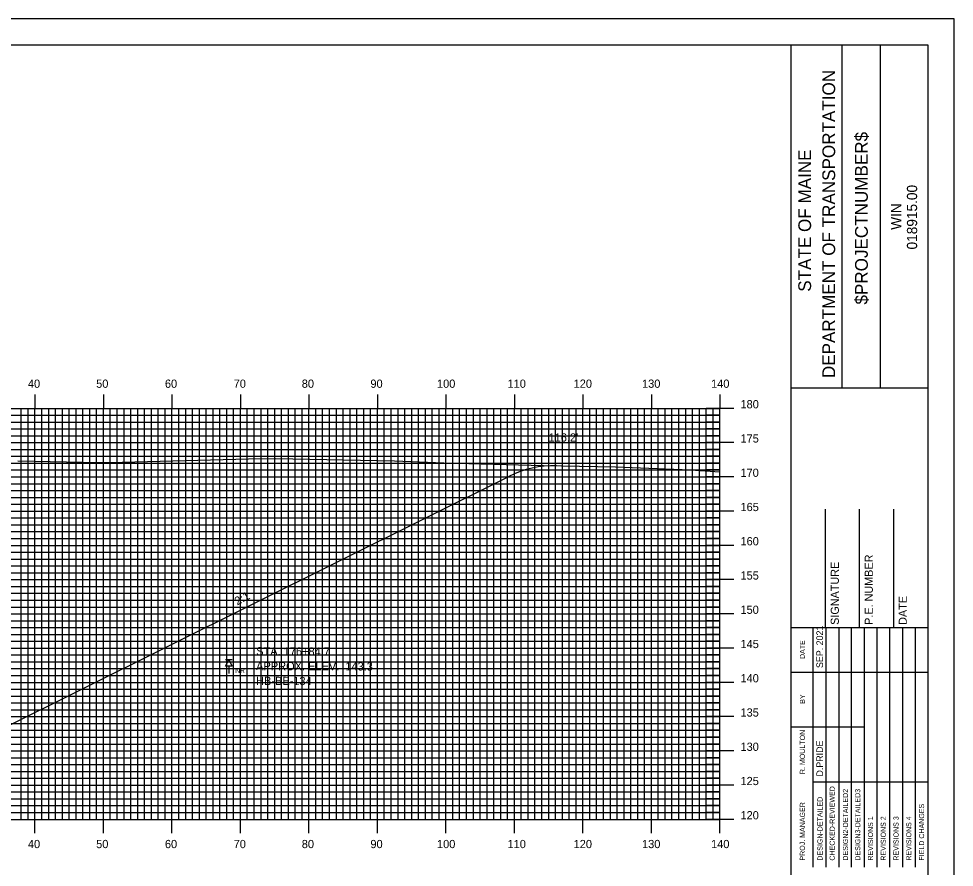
# Model space of a CAD drawing. Extents: x 1784615 to 1784958, y 442591 to 442811.
# Drawn here: x 1784818.1 to 1784954.7, y 442686.7 to 442810.5 of the extents above; entities that cross this region are included whole.
import ezdxf

# ---------------------------------------------------------------- set-up
doc = ezdxf.new("R2010")
doc.units = 0
for name, color, linetype in [('ANNOTATION', 7, 'Continuous'), ('BORDER', 7, 'Continuous'), ('BORING - NO REFUSAL', 7, 'Continuous'), ('D_Roadway_SlopeLines', 7, 'Continuous'), ('D_Text_Standard', 7, 'Continuous'), ('H_V ANNOTATION', 7, 'Continuous'), ('MAJOR', 7, 'Continuous'), ('MINOR', 7, 'Continuous'), ('PLOT BOUNDARY', 7, 'Continuous'), ('S_Roadway_Centerline', 7, 'Continuous')]:
    doc.layers.add(name, color=color, linetype=linetype)

msp = doc.modelspace()

# ---------------------------------------------------------------- linework, layer by layer
at = {"layer": 'BORDER'}
for p, q in [((1784930.91, 442596.67), (1784930.91, 442806.67)), ((1784938.37, 442756.66), (1784938.37, 442806.66)), ((1784943.96, 442756.66), (1784943.96, 442806.66)), ((1784930.91, 442756.65), (1784950.91, 442756.65)), ((1784930.91, 442756.65), (1784950.91, 442756.65)), ((1784935.91, 442721.67), (1784935.91, 442738.97)), ((1784935.91, 442721.67), (1784935.91, 442738.97)), ((1784940.91, 442721.67), (1784940.91, 442738.97)), ((1784940.91, 442721.67), (1784940.91, 442738.97)), ((1784945.91, 442721.67), (1784945.91, 442738.97)), ((1784945.91, 442721.67), (1784945.91, 442738.97)), ((1784930.91, 442721.67), (1784950.91, 442721.67)), ((1784930.91, 442721.67), (1784950.91, 442721.67))]:
    msp.add_line(p, q, dxfattribs=at)
msp.add_lwpolyline([(1784630.91, 442596.67), (1784950.91, 442596.67), (1784950.91, 442806.67), (1784630.91, 442806.67)], close=True, dxfattribs=at)
for points in [[(1784934.14, 442715.17), (1784934.14, 442721.67)], [(1784934.14, 442715.17), (1784934.14, 442721.67)], [(1784936.01, 442686.68), (1784936.01, 442721.67)], [(1784936.01, 442686.68), (1784936.01, 442721.67)], [(1784937.87, 442721.67), (1784937.87, 442686.68)], [(1784937.87, 442721.67), (1784937.87, 442686.68)], [(1784939.73, 442686.68), (1784939.73, 442721.67)], [(1784939.73, 442686.68), (1784939.73, 442721.67)], [(1784941.6, 442686.68), (1784941.6, 442721.67)], [(1784941.6, 442686.68), (1784941.6, 442721.67)], [(1784943.46, 442686.68), (1784943.46, 442721.67)], [(1784943.46, 442686.68), (1784943.46, 442721.67)], [(1784945.32, 442686.68), (1784945.32, 442721.67)], [(1784945.32, 442686.68), (1784945.32, 442721.67)], [(1784947.19, 442686.68), (1784947.19, 442721.67)], [(1784947.19, 442686.68), (1784947.19, 442721.67)], [(1784949.05, 442686.68), (1784949.05, 442721.67)], [(1784949.05, 442686.68), (1784949.05, 442721.67)], [(1784934.14, 442686.68), (1784934.14, 442720.26)], [(1784934.14, 442686.68), (1784934.14, 442720.26)], [(1784930.91, 442715.17), (1784950.91, 442715.17)], [(1784930.91, 442715.17), (1784950.91, 442715.17)], [(1784930.91, 442707.17), (1784934.14, 442707.17)], [(1784930.91, 442707.17), (1784934.14, 442707.17)], [(1784934.14, 442707.17), (1784941.6, 442707.17)], [(1784934.14, 442707.17), (1784941.6, 442707.17)], [(1784934.14, 442699.17), (1784950.91, 442699.17)], [(1784934.14, 442699.17), (1784950.91, 442699.17)]]:
    msp.add_lwpolyline(points, dxfattribs=at)
at = {"layer": 'BORING - NO REFUSAL'}
for p, q in [((1784849.29, 442716.97), (1784848.33, 442716.97)), ((1784848.81, 442716.01), (1784848.81, 442714.95))]:
    msp.add_line(p, q, dxfattribs=at)
msp.add_lwpolyline([(1784848.81, 442716.97), (1784849.29, 442716.01), (1784848.33, 442716.01)], close=True, dxfattribs=at)
at = {"layer": 'D_Roadway_SlopeLines'}
msp.add_line((1784810.7, 442704.42), (1784889.7, 442743.74), dxfattribs=at)
msp.add_arc((1784896.39, 442730.31), 15, 88.9414, 116.4579, dxfattribs=at)
at = {"layer": 'MAJOR'}
for p, q in [((1784820.51, 442755.67), (1784820.51, 442753.67)), ((1784830.51, 442755.67), (1784830.51, 442753.67)), ((1784840.51, 442755.67), (1784840.51, 442753.67)), ((1784850.51, 442755.67), (1784850.51, 442753.67)), ((1784860.51, 442755.67), (1784860.51, 442753.67)), ((1784870.51, 442755.67), (1784870.51, 442753.67)), ((1784880.51, 442755.67), (1784880.51, 442753.67)), ((1784890.51, 442755.67), (1784890.51, 442753.67)), ((1784900.51, 442755.67), (1784900.51, 442753.67)), ((1784910.51, 442755.67), (1784910.51, 442753.67)), ((1784920.51, 442755.67), (1784920.51, 442753.67)), ((1784640.51, 442753.67), (1784920.51, 442753.67)), ((1784640.51, 442753.67), (1784920.51, 442753.67)), ((1784820.51, 442693.67), (1784820.51, 442753.67)), ((1784830.51, 442693.67), (1784830.51, 442753.67)), ((1784840.51, 442693.67), (1784840.51, 442753.67)), ((1784850.51, 442693.67), (1784850.51, 442753.67)), ((1784860.51, 442693.67), (1784860.51, 442753.67)), ((1784870.51, 442693.67), (1784870.51, 442753.67)), ((1784880.51, 442693.67), (1784880.51, 442753.67)), ((1784890.51, 442693.67), (1784890.51, 442753.67)), ((1784900.51, 442693.67), (1784900.51, 442753.67)), ((1784910.51, 442693.67), (1784910.51, 442753.67)), ((1784922.52, 442753.67), (1784918.51, 442753.67)), ((1784920.51, 442693.67), (1784920.51, 442753.67)), ((1784920.51, 442693.67), (1784920.51, 442753.67)), ((1784640.51, 442748.67), (1784920.51, 442748.67)), ((1784922.52, 442748.67), (1784918.51, 442748.67)), ((1784640.51, 442743.67), (1784920.51, 442743.67)), ((1784922.52, 442743.67), (1784918.51, 442743.67)), ((1784640.51, 442738.67), (1784920.51, 442738.67)), ((1784922.52, 442738.67), (1784918.51, 442738.67)), ((1784640.51, 442733.67), (1784920.51, 442733.67)), ((1784922.52, 442733.67), (1784918.51, 442733.67)), ((1784640.51, 442728.67), (1784920.51, 442728.67)), ((1784922.52, 442728.67), (1784918.51, 442728.67)), ((1784640.51, 442723.67), (1784920.51, 442723.67)), ((1784922.52, 442723.67), (1784918.51, 442723.67)), ((1784640.51, 442718.67), (1784920.51, 442718.67)), ((1784922.52, 442718.67), (1784918.51, 442718.67)), ((1784640.51, 442713.67), (1784920.51, 442713.67)), ((1784922.52, 442713.67), (1784918.51, 442713.67)), ((1784640.51, 442708.67), (1784920.51, 442708.67)), ((1784922.52, 442708.67), (1784918.51, 442708.67)), ((1784640.51, 442703.67), (1784920.51, 442703.67)), ((1784922.52, 442703.67), (1784918.51, 442703.67)), ((1784640.51, 442698.67), (1784920.51, 442698.67)), ((1784922.52, 442698.67), (1784918.51, 442698.67)), ((1784640.51, 442693.67), (1784920.51, 442693.67)), ((1784640.51, 442693.67), (1784920.51, 442693.67)), ((1784820.51, 442691.66), (1784820.51, 442693.67)), ((1784830.51, 442691.66), (1784830.51, 442693.67)), ((1784840.51, 442691.66), (1784840.51, 442693.67)), ((1784850.51, 442691.66), (1784850.51, 442693.67)), ((1784860.51, 442691.66), (1784860.51, 442693.67)), ((1784870.51, 442691.66), (1784870.51, 442693.67)), ((1784880.51, 442691.66), (1784880.51, 442693.67)), ((1784890.51, 442691.66), (1784890.51, 442693.67)), ((1784900.51, 442691.66), (1784900.51, 442693.67)), ((1784910.51, 442691.66), (1784910.51, 442693.67)), ((1784922.52, 442693.67), (1784918.51, 442693.67)), ((1784920.51, 442691.66), (1784920.51, 442693.67))]:
    msp.add_line(p, q, dxfattribs=at)
at = {"layer": 'MINOR'}
for p, q in [((1784818.51, 442693.67), (1784818.51, 442753.67)), ((1784819.51, 442693.67), (1784819.51, 442753.67)), ((1784821.51, 442693.67), (1784821.51, 442753.67)), ((1784822.51, 442693.67), (1784822.51, 442753.67)), ((1784823.51, 442693.67), (1784823.51, 442753.67)), ((1784824.51, 442693.67), (1784824.51, 442753.67)), ((1784825.51, 442693.67), (1784825.51, 442753.67)), ((1784826.51, 442693.67), (1784826.51, 442753.67)), ((1784827.51, 442693.67), (1784827.51, 442753.67)), ((1784828.51, 442693.67), (1784828.51, 442753.67)), ((1784829.51, 442693.67), (1784829.51, 442753.67)), ((1784831.51, 442693.67), (1784831.51, 442753.67)), ((1784832.51, 442693.67), (1784832.51, 442753.67)), ((1784833.51, 442693.67), (1784833.51, 442753.67)), ((1784834.51, 442693.67), (1784834.51, 442753.67)), ((1784835.51, 442693.67), (1784835.51, 442753.67)), ((1784836.51, 442693.67), (1784836.51, 442753.67)), ((1784837.51, 442693.67), (1784837.51, 442753.67)), ((1784838.51, 442693.67), (1784838.51, 442753.67)), ((1784839.51, 442693.67), (1784839.51, 442753.67)), ((1784841.51, 442693.67), (1784841.51, 442753.67)), ((1784842.51, 442693.67), (1784842.51, 442753.67)), ((1784843.51, 442693.67), (1784843.51, 442753.67)), ((1784844.51, 442693.67), (1784844.51, 442753.67)), ((1784845.51, 442693.67), (1784845.51, 442753.67)), ((1784846.51, 442693.67), (1784846.51, 442753.67)), ((1784847.51, 442693.67), (1784847.51, 442753.67)), ((1784848.51, 442693.67), (1784848.51, 442753.67)), ((1784849.51, 442693.67), (1784849.51, 442753.67)), ((1784851.51, 442693.67), (1784851.51, 442753.67)), ((1784852.51, 442693.67), (1784852.51, 442753.67)), ((1784853.51, 442693.67), (1784853.51, 442753.67)), ((1784854.51, 442693.67), (1784854.51, 442753.67)), ((1784855.51, 442693.67), (1784855.51, 442753.67)), ((1784856.51, 442693.67), (1784856.51, 442753.67)), ((1784857.51, 442693.67), (1784857.51, 442753.67)), ((1784858.51, 442693.67), (1784858.51, 442753.67)), ((1784859.51, 442693.67), (1784859.51, 442753.67)), ((1784861.51, 442693.67), (1784861.51, 442753.67)), ((1784862.51, 442693.67), (1784862.51, 442753.67)), ((1784863.51, 442693.67), (1784863.51, 442753.67)), ((1784864.51, 442693.67), (1784864.51, 442753.67)), ((1784865.51, 442693.67), (1784865.51, 442753.67)), ((1784866.51, 442693.67), (1784866.51, 442753.67)), ((1784867.51, 442693.67), (1784867.51, 442753.67)), ((1784868.51, 442693.67), (1784868.51, 442753.67)), ((1784869.51, 442693.67), (1784869.51, 442753.67)), ((1784871.51, 442693.67), (1784871.51, 442753.67)), ((1784872.51, 442693.67), (1784872.51, 442753.67)), ((1784873.51, 442693.67), (1784873.51, 442753.67)), ((1784874.51, 442693.67), (1784874.51, 442753.67)), ((1784875.51, 442693.67), (1784875.51, 442753.67)), ((1784876.51, 442693.67), (1784876.51, 442753.67)), ((1784877.51, 442693.67), (1784877.51, 442753.67)), ((1784878.51, 442693.67), (1784878.51, 442753.67)), ((1784879.51, 442693.67), (1784879.51, 442753.67)), ((1784881.51, 442693.67), (1784881.51, 442753.67)), ((1784882.51, 442693.67), (1784882.51, 442753.67)), ((1784883.51, 442693.67), (1784883.51, 442753.67)), ((1784884.51, 442693.67), (1784884.51, 442753.67)), ((1784885.51, 442693.67), (1784885.51, 442753.67)), ((1784886.51, 442693.67), (1784886.51, 442753.67)), ((1784887.51, 442693.67), (1784887.51, 442753.67)), ((1784888.51, 442693.67), (1784888.51, 442753.67)), ((1784889.51, 442693.67), (1784889.51, 442753.67)), ((1784891.51, 442693.67), (1784891.51, 442753.67)), ((1784892.51, 442693.67), (1784892.51, 442753.67)), ((1784893.51, 442693.67), (1784893.51, 442753.67)), ((1784894.51, 442693.67), (1784894.51, 442753.67)), ((1784895.51, 442693.67), (1784895.51, 442753.67)), ((1784896.51, 442693.67), (1784896.51, 442753.67)), ((1784897.51, 442693.67), (1784897.51, 442753.67)), ((1784898.51, 442693.67), (1784898.51, 442753.67)), ((1784899.51, 442693.67), (1784899.51, 442753.67)), ((1784901.51, 442693.67), (1784901.51, 442753.67)), ((1784902.51, 442693.67), (1784902.51, 442753.67)), ((1784903.51, 442693.67), (1784903.51, 442753.67)), ((1784904.51, 442693.67), (1784904.51, 442753.67)), ((1784905.51, 442693.67), (1784905.51, 442753.67)), ((1784906.51, 442693.67), (1784906.51, 442753.67)), ((1784907.51, 442693.67), (1784907.51, 442753.67)), ((1784908.51, 442693.67), (1784908.51, 442753.67)), ((1784909.51, 442693.67), (1784909.51, 442753.67)), ((1784911.51, 442693.67), (1784911.51, 442753.67)), ((1784912.51, 442693.67), (1784912.51, 442753.67)), ((1784913.51, 442693.67), (1784913.51, 442753.67)), ((1784914.51, 442693.67), (1784914.51, 442753.67)), ((1784915.51, 442693.67), (1784915.51, 442753.67)), ((1784916.51, 442693.67), (1784916.51, 442753.67)), ((1784917.51, 442693.67), (1784917.51, 442753.67)), ((1784918.51, 442693.67), (1784918.51, 442753.67)), ((1784919.51, 442693.67), (1784919.51, 442753.67)), ((1784640.51, 442752.67), (1784920.51, 442752.67)), ((1784920.51, 442752.67), (1784918.51, 442752.67)), ((1784640.51, 442751.67), (1784920.51, 442751.67)), ((1784920.51, 442751.67), (1784918.51, 442751.67)), ((1784640.51, 442750.67), (1784920.51, 442750.67)), ((1784640.51, 442749.67), (1784920.51, 442749.67)), ((1784920.51, 442750.67), (1784918.51, 442750.67)), ((1784920.51, 442749.67), (1784918.51, 442749.67)), ((1784640.51, 442747.67), (1784920.51, 442747.67)), ((1784640.51, 442746.67), (1784920.51, 442746.67)), ((1784920.51, 442747.67), (1784918.51, 442747.67)), ((1784920.51, 442746.67), (1784918.51, 442746.67)), ((1784640.51, 442745.67), (1784920.51, 442745.67)), ((1784920.51, 442745.67), (1784918.51, 442745.67)), ((1784640.51, 442744.67), (1784920.51, 442744.67)), ((1784920.51, 442744.67), (1784918.51, 442744.67)), ((1784640.51, 442742.67), (1784920.51, 442742.67)), ((1784920.51, 442742.67), (1784918.51, 442742.67)), ((1784640.51, 442741.67), (1784920.51, 442741.67)), ((1784920.51, 442741.67), (1784918.51, 442741.67)), ((1784640.51, 442740.67), (1784920.51, 442740.67)), ((1784920.51, 442740.67), (1784918.51, 442740.67)), ((1784640.51, 442739.67), (1784920.51, 442739.67)), ((1784920.51, 442739.67), (1784918.51, 442739.67)), ((1784640.51, 442737.67), (1784920.51, 442737.67)), ((1784920.51, 442737.67), (1784918.51, 442737.67)), ((1784640.51, 442736.67), (1784920.51, 442736.67)), ((1784920.51, 442736.67), (1784918.51, 442736.67)), ((1784640.51, 442735.67), (1784920.51, 442735.67)), ((1784640.51, 442734.67), (1784920.51, 442734.67)), ((1784920.51, 442735.67), (1784918.51, 442735.67)), ((1784920.51, 442734.67), (1784918.51, 442734.67)), ((1784640.51, 442732.67), (1784920.51, 442732.67)), ((1784640.51, 442731.67), (1784920.51, 442731.67)), ((1784920.51, 442732.67), (1784918.51, 442732.67)), ((1784920.51, 442731.67), (1784918.51, 442731.67)), ((1784640.51, 442730.67), (1784920.51, 442730.67)), ((1784920.51, 442730.67), (1784918.51, 442730.67)), ((1784640.51, 442729.67), (1784920.51, 442729.67)), ((1784920.51, 442729.67), (1784918.51, 442729.67)), ((1784640.51, 442727.67), (1784920.51, 442727.67)), ((1784920.51, 442727.67), (1784918.51, 442727.67)), ((1784640.51, 442726.67), (1784920.51, 442726.67)), ((1784920.51, 442726.67), (1784918.51, 442726.67)), ((1784640.51, 442725.67), (1784920.51, 442725.67)), ((1784920.51, 442725.67), (1784918.51, 442725.67)), ((1784640.51, 442724.67), (1784920.51, 442724.67)), ((1784920.51, 442724.67), (1784918.51, 442724.67)), ((1784640.51, 442722.67), (1784920.51, 442722.67)), ((1784920.51, 442722.67), (1784918.51, 442722.67)), ((1784640.51, 442721.67), (1784920.51, 442721.67)), ((1784920.51, 442721.67), (1784918.51, 442721.67)), ((1784640.51, 442720.67), (1784920.51, 442720.67)), ((1784640.51, 442719.67), (1784920.51, 442719.67)), ((1784920.51, 442720.67), (1784918.51, 442720.67)), ((1784920.51, 442719.67), (1784918.51, 442719.67)), ((1784640.51, 442717.67), (1784920.51, 442717.67)), ((1784640.51, 442716.67), (1784920.51, 442716.67)), ((1784920.51, 442717.67), (1784918.51, 442717.67)), ((1784920.51, 442716.67), (1784918.51, 442716.67)), ((1784640.51, 442715.67), (1784920.51, 442715.67)), ((1784920.51, 442715.67), (1784918.51, 442715.67)), ((1784640.51, 442714.67), (1784920.51, 442714.67)), ((1784920.51, 442714.67), (1784918.51, 442714.67)), ((1784640.51, 442712.67), (1784920.51, 442712.67)), ((1784920.51, 442712.67), (1784918.51, 442712.67)), ((1784640.51, 442711.67), (1784920.51, 442711.67)), ((1784920.51, 442711.67), (1784918.51, 442711.67)), ((1784640.51, 442710.67), (1784920.51, 442710.67)), ((1784920.51, 442710.67), (1784918.51, 442710.67)), ((1784640.51, 442709.67), (1784920.51, 442709.67)), ((1784920.51, 442709.67), (1784918.51, 442709.67)), ((1784640.51, 442707.67), (1784920.51, 442707.67)), ((1784920.51, 442707.67), (1784918.51, 442707.67)), ((1784640.51, 442706.67), (1784920.51, 442706.67)), ((1784920.51, 442706.67), (1784918.51, 442706.67)), ((1784640.51, 442705.67), (1784920.51, 442705.67)), ((1784640.51, 442704.67), (1784920.51, 442704.67)), ((1784920.51, 442705.67), (1784918.51, 442705.67)), ((1784920.51, 442704.67), (1784918.51, 442704.67)), ((1784640.51, 442702.67), (1784920.51, 442702.67)), ((1784640.51, 442701.67), (1784920.51, 442701.67)), ((1784920.51, 442702.67), (1784918.51, 442702.67)), ((1784920.51, 442701.67), (1784918.51, 442701.67)), ((1784640.51, 442700.67), (1784920.51, 442700.67)), ((1784920.51, 442700.67), (1784918.51, 442700.67)), ((1784640.51, 442699.67), (1784920.51, 442699.67)), ((1784920.51, 442699.67), (1784918.51, 442699.67)), ((1784640.51, 442697.67), (1784920.51, 442697.67)), ((1784920.51, 442697.67), (1784918.51, 442697.67)), ((1784640.51, 442696.67), (1784920.51, 442696.67)), ((1784920.51, 442696.67), (1784918.51, 442696.67)), ((1784640.51, 442695.67), (1784920.51, 442695.67)), ((1784920.51, 442695.67), (1784918.51, 442695.67)), ((1784640.51, 442694.67), (1784920.51, 442694.67)), ((1784920.51, 442694.67), (1784918.51, 442694.67))]:
    msp.add_line(p, q, dxfattribs=at)
at = {"layer": 'PLOT BOUNDARY'}
msp.add_lwpolyline([(1784614.73, 442590.55), (1784954.73, 442590.55), (1784954.73, 442810.55), (1784614.73, 442810.55)], close=True, dxfattribs=at)
at = {"layer": 'S_Roadway_Centerline'}
msp.add_lwpolyline([(1784818.02, 442745.99), (1784829.82, 442745.75), (1784830.58, 442745.74), (1784831.37, 442745.77), (1784851.7, 442746.3), (1784855.68, 442746.33), (1784872.98, 442746), (1784880.21, 442745.73), (1784894.73, 442745.35), (1784905.28, 442745.15), (1784916.2, 442744.71), (1784920.51, 442744.38)], dxfattribs=at)

# ---------------------------------------------------------------- texts
at = {"layer": 'ANNOTATION'}
msp.add_text('2:1', height=1.2, rotation=27.5161, dxfattribs=at).set_placement((1784850.04, 442724.89))
at = {"layer": 'BORDER'}
for s, height, p in [('DEPARTMENT OF TRANSPORTATION', 1.8635, (1784937.33, 442758.08)), ('$PROJECTNUMBER$', 1.8635, (1784942.1, 442768.82)), ('STATE OF MAINE', 1.8635, (1784933.82, 442770.69)), ('018915.00', 1.491, (1784949.3, 442776.86)), ('WIN', 1.491, (1784946.99, 442779.73)), ('P.E. NUMBER', 1.1811, (1784942.83, 442722.06)), ('P.E. NUMBER', 1.1811, (1784942.83, 442722.06)), ('SIGNATURE', 1.181, (1784937.87, 442722.06)), ('SIGNATURE', 1.181, (1784937.87, 442722.06)), ('DATE', 1.181, (1784947.79, 442722.06)), ('DATE', 1.181, (1784947.79, 442722.06)), ('SEP. 2021', 0.969, (1784935.56, 442715.76)), ('DATE', 0.743, (1784932.92, 442717.08)), ('DATE', 0.743, (1784932.92, 442717.08)), ('BY', 0.743, (1784932.92, 442710.54)), ('BY', 0.743, (1784932.92, 442710.54)), ('R. MOULTON', 0.745, (1784932.92, 442700.28)), ('D.PRIDE', 0.969, (1784935.56, 442699.92)), ('CHECKED-REVIEWED', 0.7455, (1784937.27, 442687.65)), ('CHECKED-REVIEWED', 0.7455, (1784937.27, 442687.65)), ('DESIGN2-DETAILED2', 0.7455, (1784939.21, 442687.65)), ('DESIGN2-DETAILED2', 0.7455, (1784939.21, 442687.65)), ('DESIGN3-DETAILED3', 0.7455, (1784941, 442687.65)), ('DESIGN3-DETAILED3', 0.7455, (1784941, 442687.65)), ('DESIGN-DETAILED', 0.7455, (1784935.49, 442687.65)), ('DESIGN-DETAILED', 0.7455, (1784935.49, 442687.65)), ('PROJ. MANAGER', 0.7455, (1784932.92, 442687.65)), ('PROJ. MANAGER', 0.7455, (1784932.92, 442687.65)), ('FIELD CHANGES', 0.7455, (1784950.32, 442687.65)), ('FIELD CHANGES', 0.7455, (1784950.32, 442687.65)), ('REVISIONS 1', 0.7455, (1784942.86, 442687.65)), ('REVISIONS 1', 0.7455, (1784942.86, 442687.65)), ('REVISIONS 2', 0.7455, (1784944.73, 442687.65)), ('REVISIONS 2', 0.7455, (1784944.73, 442687.65)), ('REVISIONS 3', 0.7455, (1784946.59, 442687.65)), ('REVISIONS 3', 0.7455, (1784946.59, 442687.65)), ('REVISIONS 4', 0.7455, (1784948.45, 442687.65)), ('REVISIONS 4', 0.7455, (1784948.45, 442687.65))]:
    msp.add_text(s, height=height, rotation=90, dxfattribs=at).set_placement(p)
at = {"layer": 'BORING - NO REFUSAL'}
for s, p in [('STA. 176+84.7', (1784852.81, 442717.61)), ('APPROX. ELEV.  143.3', (1784852.8, 442715.45)), ('HB-BE-134', (1784852.79, 442713.29))]:
    msp.add_text(s, height=1.2, rotation=359.8142, dxfattribs=at).set_placement(p)
msp.add_text('NR', height=0.7, dxfattribs=at).set_placement((1784849.75, 442715.05))
at = {"layer": 'D_Text_Standard'}
msp.add_text("116.2'", height=1.2, dxfattribs=at).set_placement((1784895.49, 442748.82))
at = {"layer": 'H_V ANNOTATION'}
for s, p in [('40', (1784819.48, 442756.67)), ('50', (1784829.44, 442756.67)), ('60', (1784839.48, 442756.67)), ('70', (1784849.52, 442756.67)), ('80', (1784859.46, 442756.67)), ('90', (1784869.48, 442756.67)), ('100', (1784879.2, 442756.67)), ('110', (1784889.5, 442756.67)), ('120', (1784899.15, 442756.67)), ('130', (1784909.14, 442756.67)), ('140', (1784919.22, 442756.67)), ('180', (1784923.51, 442753.67)), ('175', (1784923.51, 442748.67)), ('170', (1784923.51, 442743.67)), ('165', (1784923.51, 442738.67)), ('160', (1784923.51, 442733.67)), ('155', (1784923.51, 442728.67)), ('150', (1784923.51, 442723.67)), ('145', (1784923.51, 442718.67)), ('140', (1784923.51, 442713.67)), ('135', (1784923.51, 442708.67)), ('130', (1784923.51, 442703.67)), ('125', (1784923.51, 442698.67)), ('120', (1784923.51, 442693.67)), ('40', (1784819.48, 442689.47)), ('50', (1784829.44, 442689.47)), ('60', (1784839.48, 442689.47)), ('70', (1784849.52, 442689.47)), ('80', (1784859.46, 442689.47)), ('90', (1784869.48, 442689.47)), ('100', (1784879.2, 442689.47)), ('110', (1784889.5, 442689.47)), ('120', (1784899.15, 442689.47)), ('130', (1784909.14, 442689.47)), ('140', (1784919.22, 442689.47))]:
    msp.add_text(s, height=1.2, dxfattribs=at).set_placement(p)

doc.saveas('drawing.dxf')
